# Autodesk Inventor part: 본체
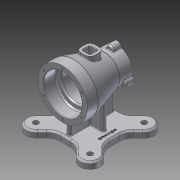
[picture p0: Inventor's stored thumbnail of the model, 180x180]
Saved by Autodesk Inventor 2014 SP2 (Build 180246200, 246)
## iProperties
Created: 2018-03
Part Number: 본체
Material: 알루미늄 6061
Document SubType Name: Modeling
Designer: 거성
Density: 2.71 g/cm^3
Appearance: 알루미늄 - 평지
Mass: 1028.95 g
Surface Area: 866.354 cm^2
Volume: 379.688 cm^3
Author: 거성
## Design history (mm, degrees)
sketch "스케치1" dims "d0" = 140
  geometry: L1 (0, 0)-(-49.497, 49.497); L2 (0, 0)-(-49.497, -49.497); L3 (0, 0)-(-70, 0); L4 (-35.239, 60.483)-(-19.755, 45); L5 (-60.483, 35.239)-(-45, 19.755); L6 (-19.755, -45)-(19.755, -45); L7 (45, -19.755)-(45, 19.755); L8 (19.755, 45)-(-19.755, 45); L9 (-45, 19.755)-(-45, -19.755); L10 (-45, -45)-(45, 45); L11 (49.497, -49.497)-(-45, 45); L12 (-35.239, -60.483)-(-19.755, -45); L13 (-60.483, -35.239)-(-45, -19.755); L14 (0, 0)-(54.385, 54.385); L15 (0, 0)-(70, 0); L16 (0, 0)-(60.568, -60.568); L17 (35.239, 60.483)-(19.755, 45); L18 (60.483, 35.239)-(45, 19.755); L19 (60.483, -35.239)-(45, -19.755); L20 (35.239, -60.483)-(19.755, -45); A1 r 18 centre (-49.497, -49.497) between (-60.483, -35.239) and (-35.239, -60.483); A2 r 18 centre (49.497, -49.497) between (35.239, -60.483) and (60.483, -35.239); A3 r 18 centre (-49.497, 49.497) between (-35.239, 60.483) and (-60.483, 35.239); A4 r 18 centre (49.497, 49.497) between (60.483, 35.239) and (35.239, 60.483); 1 further point
  constraints: 40 end point, 8 point on circle, 6 parallel, 6 perpendicular, 4 centre point, 4 point on line, 2 coincident, 2 horizontal, 1 midpoint, 16 other
  dimensions: "d1" = 45 deg angle of L3 L1; "d2" = 45 deg angle of L2 L3; "d4" = 18 radius of A1; "d5" = 90 distance between parallel lines of L6 L8; "d6" = 90 distance between parallel lines of L7 L9; "d7" = 45 deg angle of L15 L14; "d10" = 45 deg angle of L15 L16; "d11" = 18 radius of A2
extrude "돌출1" new body sketch "스케치1" distance "d12" = 12; taper "d13" = 0 deg
sketch "스케치2"
  geometry: L1 (82, 50)-(82, -50); L2 (0, -19.755)-(0, 19.755) reference; L3 (82, -50)-(109.5, -50); L4 (82, 50)-(127, 50); L5 (127, 50)-(127, 30); L6 (127, 30)-(109.5, -27); L7 (109.5, -27)-(109.5, -50); 3 further points
  constraints: 12 end point, 3 perpendicular, 2 midpoint, 1 horizontal alignment, 1 parallel, 1 vertical
  dimensions: "d14" = 82 distance between parallel lines of L1 L2; "d15" = 100 distance of L1.start L1.end; "d16" = 90 diameter of L5 L1; "d17" = 55 diameter of L7 L1; "d18" = 20 distance from line of L5.end L4; "d19" = 77 distance from line of L6.end L4
revolve "회전1" sketch "스케치2" stored, may be unused: angle "d20" = 90 deg
hole "구멍1" diameter "d23" = 70; stored, may be unused: countersink angle "d27" = 90 deg, drill point angle "d29" = 0 deg; dims "d21" = 10, "d22" = 10, "d24" = 6, "d25" = 4, "d26" = 2, "d28" = 23
hole "구멍2" diameter "d32" = 52; stored, may be unused: countersink angle "d36" = 90 deg, drill point angle "d38" = 0 deg; dims "d30" = 10, "d31" = 10, "d33" = 6, "d34" = 4, "d35" = 2, "d37" = 47
hole "구멍3" diameter "d41" = 40; stored, may be unused: countersink angle "d45" = 90 deg, drill point angle "d47" = 0 deg; dims "d39" = 10, "d40" = 10, "d42" = 6, "d43" = 4, "d44" = 2, "d46" = 30
sketch "스케치3"
  geometry: C1 r 20 at (0, 0) reference; A1 r 27.5 centre (0, 0) between (0, 27.5) and (-6.943, 26.609) reference; A2 r 7 centre (0, 27.5) between (6.943, 26.609) and (-6.943, 26.609); 1 further point
  constraints: 5 point on circle, 1 centre point, 1 vertical alignment
  dimensions: "d48" = 7 radius of A2
extrude "돌출2" join sketch "스케치3" distance "d49" = 15; taper "d50" = 0 deg
sketch "스케치4" dims "d54" = 80
  geometry: C1 r 35 at (0, 0) reference; C2 r 45 at (0, 0) reference; 3 further points
  constraints: 2 vertical alignment, 1 coincident, 2 other
hole "구멍4" sketch "스케치4" at (0, 40) diameter "d55" = 3.242; stored, may be unused: countersink angle "d59" = 90 deg, drill point angle "d61" = 118 deg; dims "d56" = 9, "d57" = 4, "d58" = 2, "d60" = 11
sketch "스케치5"
  geometry: A1 r 7 centre (-23.816, -41.25) between (-26.516, -34.792) and (-19.573, -46.817) reference; A2 r 7 centre (0, 0) between (6.943, -0.891) and (-6.943, -0.891) reference; A3 r 27.5 centre (0, -27.5) between (-6.943, -0.891) and (-26.516, -34.792) reference; 4 further points
  constraints: 2 coincident, 1 point on circle
hole "구멍5" sketch "스케치5" at (0, 0), (-23.816, -41.25), (23.779, -41.314) diameter "d65" = 3.242; stored, may be unused: countersink angle "d69" = 90 deg, drill point angle "d71" = 118 deg; dims "d66" = 9, "d67" = 4, "d68" = 2, "d70" = 11
node "작업 평면1"
sketch "스케치7"
  geometry: L1 (12.5, -12.5)-(-12.5, -12.5); L2 (-12.5, -12.5)-(-12.5, 12.5); L3 (-12.5, 12.5)-(12.5, 12.5); L4 (12.5, 12.5)-(12.5, -12.5); L5 (12.5, -12.5)-(-12.5, 12.5); L6 (-12.5, -12.5)-(12.5, 12.5); 1 further point
  constraints: 12 end point, 2 midpoint, 2 parallel, 1 horizontal, 1 perpendicular
  dimensions: "d73" = 25 distance between parallel lines of L4 L2; "d74" = 25 distance between parallel lines of L1 L3
extrude "돌출3" join sketch "스케치7" stored distance "d75" = 15; taper "d76" = 0 deg
sketch "스케치8"
  geometry: L1 (7.5, -7.5)-(-7.5, -7.5); L2 (-7.5, -7.5)-(-7.5, 7.5); L3 (-7.5, 7.5)-(7.5, 7.5); L4 (7.5, 7.5)-(7.5, -7.5); L5 (7.5, -7.5)-(-7.5, 7.5); L6 (-7.5, -7.5)-(7.5, 7.5); 1 further point
  constraints: 12 end point, 2 midpoint, 2 parallel, 1 horizontal, 1 perpendicular
  dimensions: "d77" = 15 distance between parallel lines of L4 L2; "d78" = 15 distance between parallel lines of L1 L3
extrude "돌출4" cut sketch "스케치8" distance "d79" = 30; taper "d80" = 0 deg
sketch "스케치9"
  geometry: L1 (-19.755, -45)-(19.755, -45) reference; L2 (0, -37)-(0, 37); L3 (-4, -37)-(-4, 37); L4 (4, 37)-(4, -37); A1 r 4 centre (0, -37) between (-4, -37) and (4, -37); A2 r 4 centre (0, 37) between (4, 37) and (-4, 37); 3 further points
  constraints: 8 end point, 4 point on circle, 4 tangent, 2 centre point, 2 coincident, 1 midpoint, 1 parallel, 1 perpendicular
  dimensions: "d81" = 74 distance of L2.start L2.end; "d82" = 4 radius of A2
extrude "돌출5" join sketch "스케치9" stored distance "d85" = 30; taper "d86" = 0 deg
sketch "스케치10"
  geometry: L1 (19.755, 45)-(-19.755, 45) reference; L2 (-24, 0)-(24, 0); L3 (-24, -4)-(24, -4); L4 (24, 4)-(-24, 4); A1 r 4 centre (-24, 0) between (-24, 4) and (-24, -4); A2 r 4 centre (24, 0) between (24, -4) and (24, 4); 1 further point
  constraints: 8 end point, 4 point on circle, 4 tangent, 2 centre point, 2 parallel, 1 midpoint
  dimensions: "d87" = 48 distance of L2.end L2.start; "d88" = 4 radius of A2
extrude "돌출6" join sketch "스케치10" stored distance "d89" = 30; taper "d90" = 0 deg
fillet "모깎기1" dims "d91" = 8
fillet "모깎기2" dims "d92" = 3
chamfer "모따기1" distance "d93" = 1; stored, may be unused: second distance "d94" = 2, angle "d95" = 45 deg
fillet "모깎기3" dims "d96" = 1
fillet "모깎기4" dims "d97" = 25
chamfer "모따기2" distance "d98" = 3; stored, may be unused: second distance "d99" = 2, angle "d100" = 45 deg
chamfer "모따기3" distance "d101" = 3; stored, may be unused: second distance "d102" = 2, angle "d103" = 45 deg
chamfer "모따기4" distance "d104" = 3; stored, may be unused: second distance "d105" = 2, angle "d106" = 45 deg
chamfer "모따기5" distance "d107" = 3; stored, may be unused: second distance "d108" = 2, angle "d109" = 45 deg
chamfer "모따기6" distance "d110" = 3; stored, may be unused: second distance "d111" = 2, angle "d112" = 45 deg
chamfer "모따기7" distance "d113" = 3; stored, may be unused: second distance "d114" = 2, angle "d115" = 45 deg
chamfer "모따기8" distance "d116" = 3; stored, may be unused: second distance "d117" = 2, angle "d118" = 45 deg
fillet "모깎기5" dims "d119" = 1
fillet "모깎기6" dims "d120" = 3
fillet "모깎기7" dims "d121" = 3
fillet "모깎기8" dims "d122" = 3
fillet "모깎기9" dims "d123" = 3
fillet "모깎기10" dims "d124" = 3
fillet "모깎기11" dims "d125" = 3
chamfer "모따기9" distance "d126" = 1; stored, may be unused: second distance "d127" = 2, angle "d128" = 45 deg
chamfer "모따기10" distance "d129" = 1; stored, may be unused: second distance "d130" = 2, angle "d131" = 45 deg
fillet "모깎기12" dims "d132" = 3
fillet "모깎기13" dims "d133" = 1
hole "구멍6" diameter "d136" = 10; stored, may be unused: countersink angle "d140" = 90 deg, drill point angle "d142" = 118 deg; dims "d134" = 10, "d135" = 10, "d137" = 9, "d138" = 4, "d139" = 2, "d141" = 11
hole "구멍7" diameter "d145" = 10; stored, may be unused: countersink angle "d149" = 90 deg, drill point angle "d151" = 118 deg; dims "d143" = 10, "d144" = 10, "d146" = 9, "d147" = 4, "d148" = 2, "d150" = 11
hole "구멍8" diameter "d154" = 10; stored, may be unused: countersink angle "d158" = 90 deg, drill point angle "d160" = 118 deg; dims "d152" = 10, "d153" = 10, "d155" = 9, "d156" = 4, "d157" = 2, "d159" = 11
hole "구멍9" diameter "d163" = 10; stored, may be unused: countersink angle "d167" = 90 deg, drill point angle "d169" = 118 deg; dims "d161" = 10, "d162" = 10, "d164" = 9, "d165" = 4, "d166" = 2, "d168" = 11
fillet "모깎기14" dims "d170" = 3
fillet "모깎기15" dims "d171" = 1
fillet "모깎기16" dims "d172" = 3
fillet "모깎기17" dims "d173" = 1
sketch "스케치11"
  geometry: L1 (32.5, -20.5)-(32.5, 14.5); L2 (32.5, 14.5)-(37.5, 14.5); L3 (37.5, 14.5)-(37.5, -20.5); L4 (37.5, -20.5)-(32.5, -20.5); L5 (35, -20.5)-(35, 14.5); L6 (32.5, -3)-(37.5, -3); 2 further points
  constraints: 4 end point, 4 midpoint, 2 other
  dimensions: "d174" = 5 distance between parallel lines of L3 L1; "d175" = 35 distance between parallel lines of L2 L4; "d176" = 35 distance from line of L5 point (0, 0); "d177" = 45 distance from line of point (0, 42) L6
feature "엠보싱1" sketch "스케치11" dims "d0" = 140, "d1" = 45 deg, "d2" = 45 deg, "d4" = 18, "d5" = 90, "d6" = 90, "d7" = 45 deg, "d10" = 45 deg, "d11" = 18, "d178" = 0.5, "d179" = 0
fillet "모깎기18" dims "d180" = 3
node "솔리드1"
pattern_circular "원형 패턴1" dims angle "d52" = 360 deg
pattern_circular "원형 패턴2" dims angle "d63" = 360 deg
other parameters: "d3" = 18, "d9" = 18, "d72" = 127
